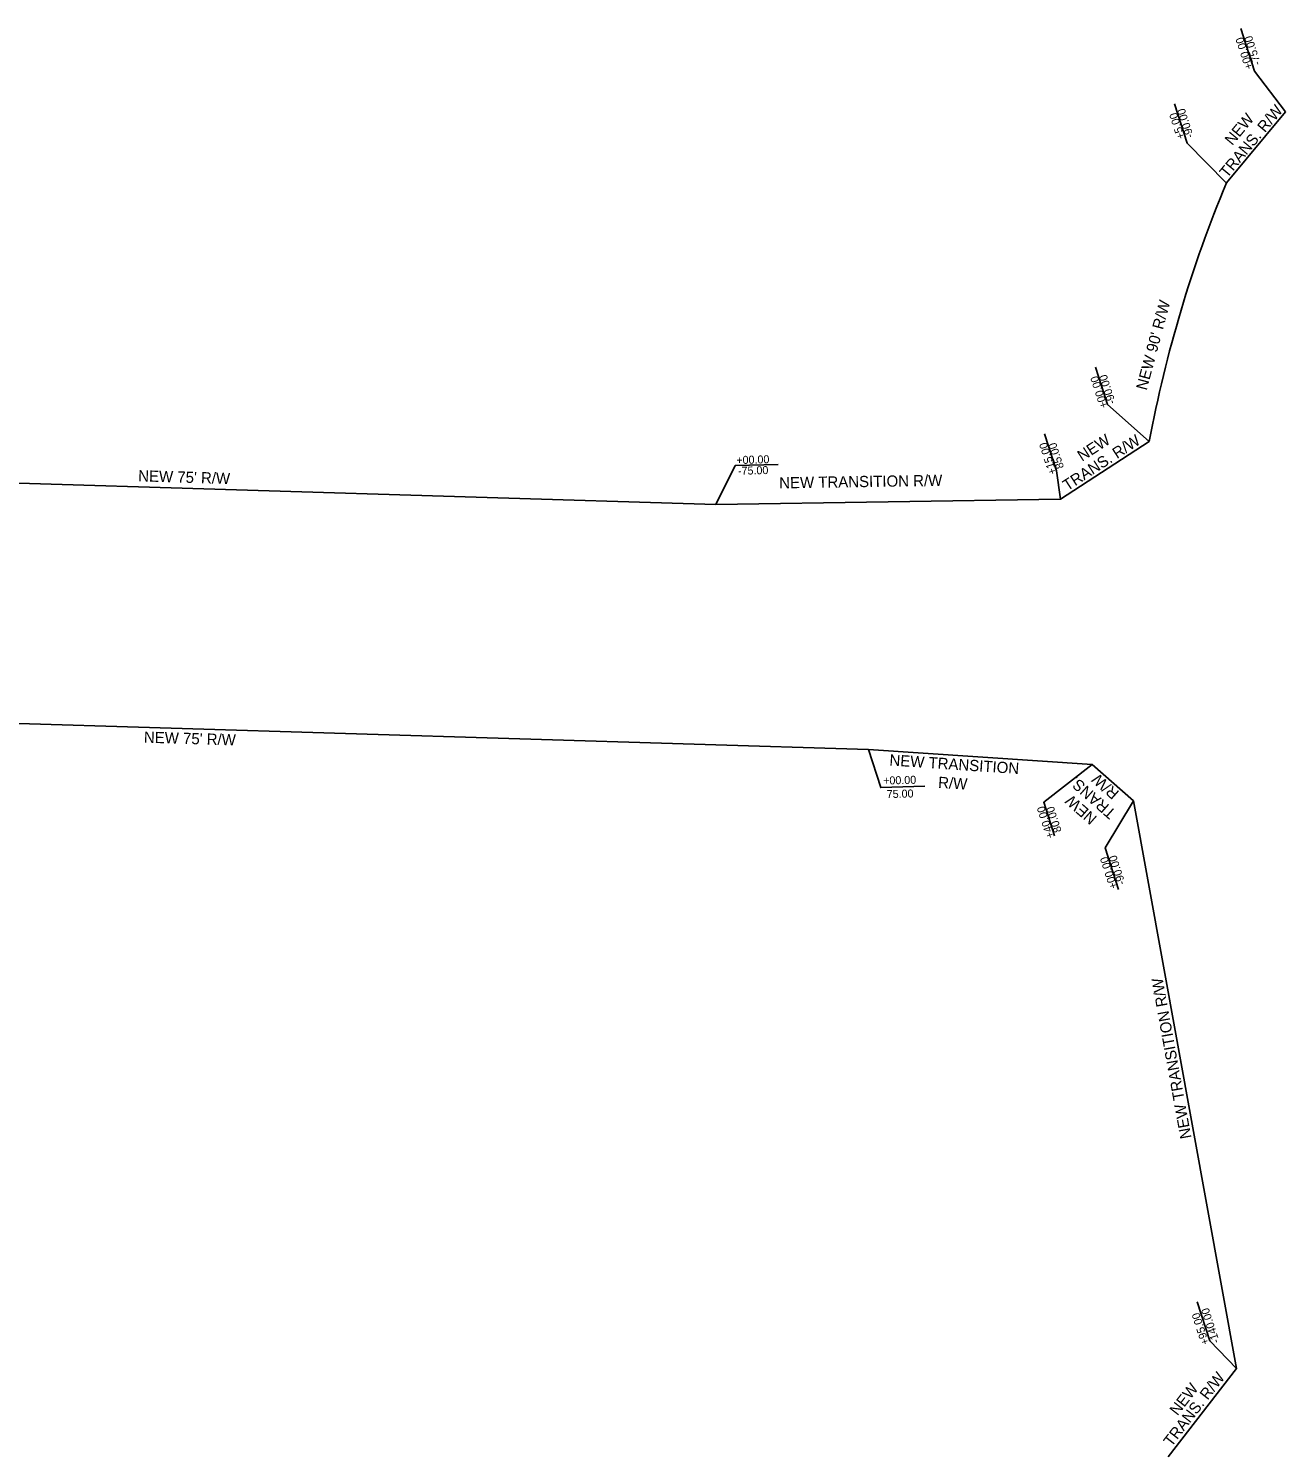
# Model space of a CAD drawing. Extents: x 2003184 to 2010449, y 855784 to 861212.
# Drawn here: x 2007629 to 2008415, y 857589 to 858477 of the extents above; entities that cross this region are included whole.
import ezdxf

# ---------------------------------------------------------------- set-up
doc = ezdxf.new("R2010")
doc.units = 0
doc.layers.add('RD_PD_RW', color=7, linetype='Continuous')
doc.layers.add('RD_PD_RW_TX', color=7, linetype='Continuous')

msp = doc.modelspace()

# ---------------------------------------------------------------- linework, layer by layer
at = {"layer": 'RD_PD_RW'}
for p, q in [((2008377.85, 858380.63), (2008414.75, 858425.08)), ((2008274.05, 858183.02), (2008329.63, 858219)), ((2007259.22, 858204.16), (2008058.84, 858179.62)), ((2008058.84, 858179.62), (2008274.05, 858183.02)), ((2007254.62, 858054.23), (2008154.19, 858026.62)), ((2008154.19, 858026.62), (2008293.97, 858017.33)), ((2008319.8, 857994.64), (2008293.97, 858017.33)), ((2008384.03, 857639.79), (2008319.8, 857994.64)), ((2008341.44, 857584.77), (2008384.03, 857639.79))]:
    msp.add_line(p, q, dxfattribs=at)
msp.add_arc((2009117.04, 858072.11), 801, 157.34528, 169.433, dxfattribs=at)
at = {"layer": 'RD_PD_RW_TX'}
for points in [[(2008386.77, 858477.13), (2008395.41, 858450.4), (2008414.75, 858425.08)], [(2008345.44, 858429.94), (2008353.34, 858405.51), (2008377.55, 858380.76)], [(2008296.02, 858265.45), (2008303.51, 858242.28), (2008329.63, 858219)], [(2008264.07, 858223.95), (2008271.55, 858200.78), (2008274.05, 858183.02)], [(2008097.66, 858204.78), (2008070.9, 858204.03), (2008058.84, 858179.62)], [(2008189.28, 858003.65), (2008161.87, 858002.88), (2008154.19, 858026.62)], [(2008270.46, 857972.67), (2008263.69, 857993.63), (2008293.97, 858017.33)], [(2008310.47, 857939.14), (2008302.04, 857965.23), (2008319.8, 857994.64)], [(2008359.52, 857681.5), (2008367.37, 857657.19), (2008384.03, 857639.79)]]:
    msp.add_lwpolyline(points, dxfattribs=at)

# ---------------------------------------------------------------- texts
for s, height, rotation, p in [('+00.00', 5, 107.9072, (2008394.47, 858452.49)), ('-75.00', 5, 107.9072, (2008399.44, 858454.99)), ('TRANS. R/W', 7, 50.29059, (2008378.26, 858383.25)), ('+5.00', 5, 107.9072, (2008351.9, 858408.87)), ('-90.00', 5, 107.9072, (2008357.45, 858409.58)), ('NEW', 7, 50.29059, (2008381.49, 858403.57)), ("NEW 90' R/W", 7, 75.06061, (2008327.98, 858250.66)), ('+00.00', 5, 107.9072, (2008303.72, 858240.81)), ('-90.00', 5, 107.9072, (2008308.69, 858243.31)), ('NEW', 7, 32.9181, (2008287.59, 858206.38)), ('+15.00', 5, 107.9072, (2008271.77, 858199.31)), ('85.00', 5, 107.9072, (2008276.39, 858202.88)), ('TRANS. R/W', 7, 32.9181, (2008278.44, 858187.95)), ('+00.00', 5, 1.60931, (2008071.69, 858204.93)), ("NEW 75' R/W", 7, 358.24216, (2007697.83, 858194.2)), ('-75.00', 5, 1.60931, (2008072.73, 858198.21)), ('NEW TRANSITION R/W', 7, 0.9052, (2008098.43, 858189.73)), ("NEW 75' R/W", 7, 358.24216, (2007701.4, 858030.9)), ('NEW TRANSITION', 7, 356.19676, (2008167.12, 858016.66)), ('R/W', 7, 138.69511, (2008311.32, 858000.13)), ('+00.00', 5, 1.60931, (2008163.42, 858004.68)), ('75.00', 5, 1.60931, (2008165.64, 857996.23)), ('R/W', 7, 356.19676, (2008197.54, 858002.71)), ('TRANS.', 7, 138.69511, (2008309.4, 857987.84)), ('NEW', 7, 138.69511, (2008297.46, 857984.36)), ('+40.00', 5, 107.9072, (2008270.32, 857972.05)), ('80.00', 5, 107.9072, (2008274.95, 857975.63)), ('+00.00', 5, 107.9072, (2008309.78, 857940.47)), ('-90.00', 5, 107.9072, (2008314.75, 857942.98)), ('NEW TRANSITION R/W', 7, 100.26051, (2008356.01, 857784.05)), ('+95.00', 5, 107.9072, (2008367.1, 857655.58)), ('-140.00', 5, 107.9072, (2008373.61, 857656.6)), ('TRANS. R/W', 7, 52.26241, (2008343.47, 857590.56)), ('NEW', 7, 52.26241, (2008347.28, 857609.98))]:
    msp.add_text(s, height=height, rotation=rotation, dxfattribs=at).set_placement(p)

doc.saveas('drawing.dxf')
